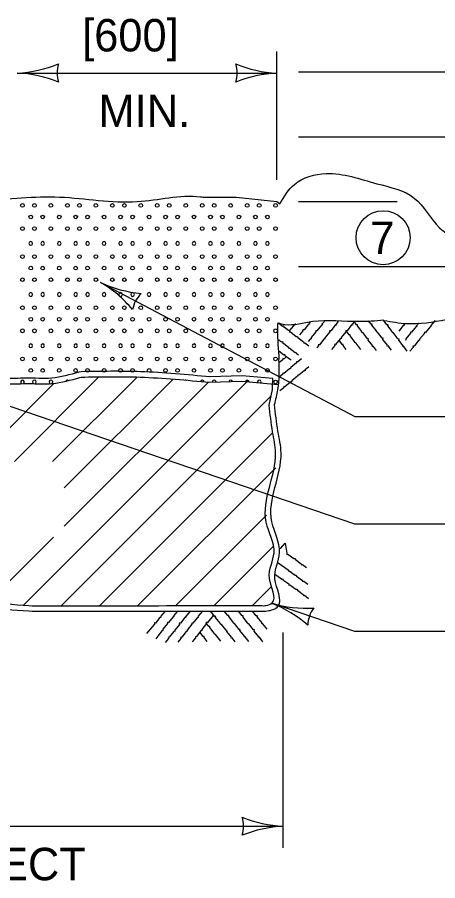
# Model space of a CAD drawing. Extents: x 49991.4 to 50021, y 49987.6 to 50011.4.
# Drawn here: x 50003.835 to 50004.612, y 49988.821 to 49990.418 of the extents above; entities that cross this region are included whole.
import ezdxf

# ---------------------------------------------------------------- set-up
doc = ezdxf.new("R2010")
doc.units = 0
for name, color, linetype in [('Level 1', 7, 'Continuous'), ('Level 2', 7, 'Continuous'), ('Level 3', 7, 'Continuous')]:
    doc.layers.add(name, color=color, linetype=linetype)

msp = doc.modelspace()

# ---------------------------------------------------------------- linework, layer by layer
at = {"layer": 'Level 1'}
for p, q in [((50004.3551, 49990.3172), (50005.5769, 49990.3172)), ((50004.3551, 49990.1972), (50005.5769, 49990.1972)), ((50004.3551, 49990.0772), (50004.5374, 49990.0772)), ((50004.3551, 49989.9572), (50004.5826, 49989.9572)), ((50004.5826, 49989.9572), (50004.6739, 49989.9572)), ((50003.8297, 49989.5967), (50003.9858, 49989.7528)), ((50003.9004, 49989.5967), (50004.0565, 49989.7527)), ((50003.922, 49989.5476), (50004.1231, 49989.7486)), ((50003.953, 49989.7625), (50003.9487, 49989.7618)), ((50003.9509, 49989.752), (50003.953, 49989.7525)), ((50003.759, 49989.5967), (50003.9033, 49989.741)), ((50003.846, 49989.3302), (50004.261, 49989.7452)), ((50003.922, 49989.4769), (50004.1883, 49989.7431)), ((50003.9163, 49989.3297), (50004.3046, 49989.718)), ((50004.3008, 49989.7004), (50004.3071, 49989.7297)), ((50003.987, 49989.3297), (50004.3073, 49989.65)), ((50004.0578, 49989.3298), (50004.3128, 49989.5848)), ((50004.1285, 49989.3298), (50004.296, 49989.4973)), ((50003.7779, 49989.3328), (50003.9018, 49989.4567)), ((50004.1992, 49989.3298), (50004.3083, 49989.4389)), ((50004.27, 49989.3299), (50004.3045, 49989.3644)), ((50004.089, 49989.2957), (50004.0739, 49989.278)), ((50004.0887, 49989.297), (50004.089, 49989.2957))]:
    msp.add_line(p, q, dxfattribs=at)
for points in [[(50004.1787, 49990.0855), (50004.2396, 49990.0851), (50004.315, 49990.0772), (50004.3207, 49990.0731)], [(50004.318, 49989.853), (50004.3256, 49989.8469), (50004.3272, 49989.8477), (50004.3273, 49989.8461), (50004.3381, 49989.838), (50004.3381, 49989.8358), (50004.3401, 49989.8361), (50004.351, 49989.8277), (50004.353, 49989.8277), (50004.3537, 49989.8258), (50004.3645, 49989.8178), (50004.3646, 49989.8158), (50004.3666, 49989.8162), (50004.374, 49989.8104)], [(50004.3487, 49989.8515), (50004.3486, 49989.8514), (50004.3494, 49989.8498), (50004.3478, 49989.8498), (50004.3392, 49989.8394), (50004.3381, 49989.8394)], [(50004.3774, 49989.8554), (50004.3745, 49989.8521), (50004.3753, 49989.8505), (50004.3737, 49989.8505), (50004.3652, 49989.8401), (50004.363, 49989.8401), (50004.3633, 49989.8381), (50004.357, 49989.8305)], [(50004.4029, 49989.8554), (50004.3984, 49989.8502), (50004.3991, 49989.8486), (50004.3975, 49989.8486), (50004.389, 49989.8382), (50004.3868, 49989.8382), (50004.3871, 49989.8362), (50004.3783, 49989.8256), (50004.3782, 49989.8236), (50004.3763, 49989.8229), (50004.3728, 49989.8184)], [(50004.4284, 49989.8551), (50004.424, 49989.85), (50004.4247, 49989.8484), (50004.4231, 49989.8484), (50004.4146, 49989.8379), (50004.4125, 49989.838), (50004.4127, 49989.836), (50004.4039, 49989.8254), (50004.4038, 49989.8234), (50004.402, 49989.8227), (50004.3936, 49989.8123), (50004.3916, 49989.8122), (50004.3919, 49989.8102), (50004.3892, 49989.8069)], [(50004.4583, 49989.8553), (50004.4541, 49989.8504), (50004.4549, 49989.8488), (50004.4533, 49989.8489), (50004.4447, 49989.8384), (50004.4426, 49989.8385), (50004.4428, 49989.8365), (50004.434, 49989.8259), (50004.434, 49989.8239), (50004.4321, 49989.8232), (50004.4237, 49989.8128), (50004.4217, 49989.8127), (50004.422, 49989.8107), (50004.416, 49989.8035)], [(50004.499, 49989.8019), (50004.4937, 49989.8092), (50004.4919, 49989.8088), (50004.4924, 49989.8103), (50004.4841, 49989.821), (50004.4846, 49989.8231), (50004.4826, 49989.8233), (50004.4743, 49989.8343), (50004.4723, 49989.8348), (50004.4721, 49989.8367), (50004.4639, 49989.8473), (50004.4642, 49989.8493), (50004.4622, 49989.8494), (50004.4578, 49989.8552)], [(50004.5268, 49989.8021), (50004.5207, 49989.8104), (50004.5189, 49989.81), (50004.5193, 49989.8116), (50004.5111, 49989.8222), (50004.5116, 49989.8243), (50004.5096, 49989.8246), (50004.5013, 49989.8355), (50004.4993, 49989.836), (50004.4991, 49989.838), (50004.4909, 49989.8485), (50004.4912, 49989.8505), (50004.4892, 49989.8506), (50004.4846, 49989.8567)], [(50004.5561, 49989.8007), (50004.55, 49989.809), (50004.5483, 49989.8086), (50004.5487, 49989.8102), (50004.5404, 49989.8209), (50004.541, 49989.8229), (50004.5389, 49989.8232), (50004.5306, 49989.8341), (50004.5287, 49989.8346), (50004.5285, 49989.8366), (50004.5202, 49989.8471), (50004.5206, 49989.8492), (50004.5185, 49989.8492), (50004.5119, 49989.8581)], [(50004.5519, 49989.8522), (50004.5496, 49989.8495), (50004.5504, 49989.8479), (50004.5488, 49989.8479), (50004.5403, 49989.8374)], [(50004.578, 49989.8529), (50004.5734, 49989.8476), (50004.5742, 49989.8459), (50004.5726, 49989.846), (50004.5641, 49989.8355), (50004.5619, 49989.8356), (50004.5621, 49989.8335), (50004.5533, 49989.823), (50004.5533, 49989.8209), (50004.5528, 49989.8207)], [(50004.6075, 49989.8572), (50004.5991, 49989.8473), (50004.5998, 49989.8457), (50004.5982, 49989.8458), (50004.5897, 49989.8353), (50004.5875, 49989.8353), (50004.5878, 49989.8333), (50004.579, 49989.8227), (50004.5789, 49989.8207), (50004.577, 49989.8201), (50004.5686, 49989.8097), (50004.5666, 49989.8095), (50004.567, 49989.8075), (50004.5609, 49989.8004)], [(50004.4702, 49989.8034), (50004.4608, 49989.8158), (50004.4589, 49989.8163), (50004.4587, 49989.8183), (50004.4504, 49989.8289), (50004.4508, 49989.8309), (50004.4487, 49989.831), (50004.4432, 49989.8384)], [(50004.317, 49989.8228), (50004.3236, 49989.8175), (50004.3252, 49989.8183), (50004.3252, 49989.8167), (50004.336, 49989.8085), (50004.336, 49989.8064), (50004.338, 49989.8067), (50004.3489, 49989.7983), (50004.3509, 49989.7983), (50004.3516, 49989.7964), (50004.3553, 49989.7937)], [(50004.4434, 49989.8035), (50004.4375, 49989.811), (50004.4379, 49989.813), (50004.4358, 49989.8131), (50004.4302, 49989.8207)], [(50004.3181, 49989.8016), (50004.3277, 49989.7938), (50004.3293, 49989.7947), (50004.3293, 49989.7931), (50004.3401, 49989.7849), (50004.3401, 49989.7838)], [(50004.3603, 49989.7862), (50004.3535, 49989.7806), (50004.3514, 49989.781), (50004.3512, 49989.779), (50004.3406, 49989.7703), (50004.3401, 49989.7683), (50004.3382, 49989.7681), (50004.3279, 49989.7594), (50004.3259, 49989.7597), (50004.3259, 49989.7577), (50004.3186, 49989.7518)], [(50004.3325, 49989.79), (50004.3283, 49989.7864), (50004.3263, 49989.7867), (50004.3263, 49989.7846), (50004.3189, 49989.7788)], [(50004.3741, 49989.7714), (50004.3671, 49989.7659), (50004.3676, 49989.7641), (50004.366, 49989.7645), (50004.3556, 49989.7559), (50004.3535, 49989.7563), (50004.3533, 49989.7543), (50004.3427, 49989.7456), (50004.3422, 49989.7436), (50004.3403, 49989.7434), (50004.33, 49989.7347), (50004.328, 49989.735), (50004.328, 49989.7329), (50004.3207, 49989.7271)], [(50004.3075, 49989.7498), (50004.2508, 49989.7548), (50004.1907, 49989.7529)], [(50004.191, 49989.7429), (50004.2505, 49989.7448), (50004.3174, 49989.7388)], [(50004.3192, 49989.4364), (50004.3206, 49989.4353), (50004.3222, 49989.4362), (50004.3302, 49989.4455), (50004.3332, 49989.4267), (50004.3333, 49989.4246), (50004.3353, 49989.4249), (50004.3464, 49989.4168), (50004.3484, 49989.4169), (50004.3492, 49989.415), (50004.3601, 49989.4073), (50004.3603, 49989.4053), (50004.3623, 49989.4058), (50004.3698, 49989.4002)], [(50004.3175, 49989.409), (50004.3356, 49989.396), (50004.3356, 49989.3939), (50004.3377, 49989.3942), (50004.3487, 49989.3861), (50004.3508, 49989.3862), (50004.3515, 49989.3844), (50004.3625, 49989.3766), (50004.3627, 49989.3746), (50004.3647, 49989.3751), (50004.3721, 49989.3695)], [(50004.3125, 49989.3876), (50004.3243, 49989.3785), (50004.3259, 49989.3794), (50004.326, 49989.3778), (50004.3369, 49989.3699), (50004.337, 49989.3678), (50004.339, 49989.3681), (50004.3501, 49989.36), (50004.3521, 49989.3601), (50004.3529, 49989.3582), (50004.3638, 49989.3505), (50004.364, 49989.3485), (50004.3661, 49989.349), (50004.3735, 49989.3433)], [(50004.1082, 49989.3198), (50004.0997, 49989.3097), (50004.1005, 49989.3081), (50004.0989, 49989.3081), (50004.0905, 49989.2975), (50004.0884, 49989.2975)], [(50004.1314, 49989.3198), (50004.1239, 49989.3109), (50004.1247, 49989.3093), (50004.1231, 49989.3093), (50004.1148, 49989.2987), (50004.1126, 49989.2987), (50004.1129, 49989.2967), (50004.1043, 49989.286), (50004.1043, 49989.2839), (50004.1024, 49989.2832), (50004.0912, 49989.2687)], [(50004.1545, 49989.3198), (50004.1458, 49989.3094), (50004.1466, 49989.3078), (50004.145, 49989.3078), (50004.1367, 49989.2972), (50004.1345, 49989.2972), (50004.1348, 49989.2952), (50004.1262, 49989.2845), (50004.1262, 49989.2825), (50004.1243, 49989.2818), (50004.1161, 49989.2712), (50004.1141, 49989.271), (50004.1145, 49989.269), (50004.1086, 49989.2618)], [(50004.1773, 49989.3198), (50004.1688, 49989.3097), (50004.1697, 49989.3081), (50004.1681, 49989.3081), (50004.1597, 49989.2975), (50004.1576, 49989.2975), (50004.1578, 49989.2955), (50004.1492, 49989.2847), (50004.1492, 49989.2827), (50004.1474, 49989.282), (50004.1392, 49989.2714), (50004.1372, 49989.2713), (50004.1375, 49989.2693), (50004.1316, 49989.2621)], [(50004.2378, 49989.2631), (50004.2324, 49989.2702), (50004.2306, 49989.2698), (50004.231, 49989.2714), (50004.2225, 49989.2819), (50004.223, 49989.284), (50004.221, 49989.2842), (50004.2125, 49989.295), (50004.2105, 49989.2954), (50004.2103, 49989.2974), (50004.2018, 49989.3078), (50004.2021, 49989.3098), (50004.2001, 49989.3099), (50004.1925, 49989.3198)], [(50004.2629, 49989.2638), (50004.2566, 49989.272), (50004.2549, 49989.2716), (50004.2552, 49989.2731), (50004.2468, 49989.2836), (50004.2473, 49989.2857), (50004.2452, 49989.2859), (50004.2367, 49989.2967), (50004.2347, 49989.2972), (50004.2345, 49989.2992), (50004.226, 49989.3095), (50004.2263, 49989.3115), (50004.2243, 49989.3116), (50004.2178, 49989.3199)], [(50004.2893, 49989.263), (50004.283, 49989.2712), (50004.2813, 49989.2708), (50004.2816, 49989.2723), (50004.2732, 49989.2828), (50004.2737, 49989.2849), (50004.2716, 49989.2851), (50004.2631, 49989.2959), (50004.2612, 49989.2964), (50004.2609, 49989.2983), (50004.2525, 49989.3087), (50004.2528, 49989.3107), (50004.2507, 49989.3108), (50004.2438, 49989.3199)], [(50004.2972, 49989.286), (50004.2893, 49989.296), (50004.2873, 49989.2965), (50004.2871, 49989.2985), (50004.2786, 49989.3089), (50004.2789, 49989.3109), (50004.2768, 49989.3109), (50004.27, 49989.3199)], [(50004.1978, 49989.3129), (50004.1959, 49989.3108), (50004.1968, 49989.3092), (50004.1951, 49989.3092), (50004.1868, 49989.2986), (50004.1847, 49989.2986), (50004.1849, 49989.2965), (50004.1763, 49989.2858), (50004.1763, 49989.2838), (50004.1745, 49989.2831), (50004.1663, 49989.2725), (50004.1643, 49989.2724), (50004.1646, 49989.2704), (50004.1587, 49989.2631)], [(50004.2111, 49989.2641), (50004.2015, 49989.2763), (50004.1995, 49989.2768), (50004.1993, 49989.2787), (50004.1908, 49989.2891), (50004.1911, 49989.2911), (50004.1891, 49989.2912), (50004.1834, 49989.2985)], [(50004.1863, 49989.2636), (50004.1803, 49989.271), (50004.1806, 49989.273), (50004.1785, 49989.273), (50004.1727, 49989.2806)]]:
    msp.add_lwpolyline(points, dxfattribs=at)
for centre in [(50003.8446, 49990.07), (50003.8668, 49990.07), (50003.8972, 49990.07), (50003.9277, 49990.07), (50003.9499, 49990.07), (50003.9803, 49990.07), (50004.0108, 49990.07), (50004.033, 49990.07), (50004.0634, 49990.07), (50004.0939, 49990.07), (50004.1161, 49990.07), (50004.1465, 49990.07), (50004.177, 49990.07), (50004.1992, 49990.07), (50004.2296, 49990.07), (50004.2601, 49990.07), (50004.2823, 49990.07), (50004.3127, 49990.07), (50003.8599, 49990.0487), (50003.882, 49990.0487), (50003.9125, 49990.0487), (50003.9125, 49990.0487), (50003.943, 49990.0487), (50003.9651, 49990.0487), (50003.9956, 49990.0487), (50003.9956, 49990.0487), (50004.0261, 49990.0487), (50004.0482, 49990.0487), (50004.0787, 49990.0487), (50004.0787, 49990.0487), (50004.1092, 49990.0487), (50004.1313, 49990.0487), (50004.1618, 49990.0487), (50004.1618, 49990.0487), (50004.1923, 49990.0487), (50004.2144, 49990.0487), (50004.2449, 49990.0487), (50004.2449, 49990.0487), (50004.2754, 49990.0487), (50004.2975, 49990.0487), (50003.8446, 49990.0273), (50003.8668, 49990.0273), (50003.8972, 49990.0273), (50003.9277, 49990.0273), (50003.9499, 49990.0273), (50003.9803, 49990.0273), (50004.0108, 49990.0273), (50004.033, 49990.0273), (50004.0634, 49990.0273), (50004.0939, 49990.0273), (50004.1161, 49990.0273), (50004.1465, 49990.0273), (50004.177, 49990.0273), (50004.1992, 49990.0273), (50004.2296, 49990.0273), (50004.2601, 49990.0273), (50004.2823, 49990.0273), (50004.3127, 49990.0273), (50003.8446, 49989.9754), (50003.8668, 49989.9754), (50003.8972, 49989.9754), (50003.9277, 49989.9754), (50003.9499, 49989.9754), (50003.9803, 49989.9754), (50004.0108, 49989.9754), (50004.033, 49989.9754), (50004.0634, 49989.9754), (50004.0939, 49989.9754), (50004.1161, 49989.9754), (50004.1465, 49989.9754), (50004.177, 49989.9754), (50004.1992, 49989.9754), (50004.2296, 49989.9754), (50004.2601, 49989.9754), (50004.2823, 49989.9754), (50004.3127, 49989.9754), (50003.8599, 49989.9541), (50003.882, 49989.9541), (50003.9125, 49989.9541), (50003.9125, 49989.9541), (50003.943, 49989.9541), (50003.9651, 49989.9541), (50003.9956, 49989.9541), (50003.9956, 49989.9541), (50004.0261, 49989.9541), (50004.0482, 49989.9541), (50004.0787, 49989.9541), (50004.0787, 49989.9541), (50004.1092, 49989.9541), (50004.1313, 49989.9541), (50004.1618, 49989.9541), (50004.1618, 49989.9541), (50004.1923, 49989.9541), (50004.2144, 49989.9541), (50004.2449, 49989.9541), (50004.2449, 49989.9541), (50004.2754, 49989.9541), (50004.2975, 49989.9541), (50003.8446, 49989.9327), (50003.8668, 49989.9327), (50003.8972, 49989.9327), (50003.9277, 49989.9327), (50003.9499, 49989.9327), (50003.9803, 49989.9327), (50004.0108, 49989.9327), (50004.033, 49989.9327), (50004.0634, 49989.9327), (50004.0939, 49989.9327), (50004.1161, 49989.9327), (50004.1465, 49989.9327), (50004.177, 49989.9327), (50004.1992, 49989.9327), (50004.2296, 49989.9327), (50004.2601, 49989.9327), (50004.2823, 49989.9327), (50004.3127, 49989.9327), (50003.8446, 49989.8808), (50003.8668, 49989.8808), (50003.8972, 49989.8808), (50003.9277, 49989.8808), (50003.9499, 49989.8808), (50003.9803, 49989.8808), (50004.0108, 49989.8808), (50004.033, 49989.8808), (50004.0634, 49989.8808), (50004.0939, 49989.8808), (50004.1161, 49989.8808), (50004.1465, 49989.8808), (50004.177, 49989.8808), (50004.1992, 49989.8808), (50004.2296, 49989.8808), (50004.2601, 49989.8808), (50004.2823, 49989.8808), (50004.3127, 49989.8808), (50003.8599, 49989.8595), (50003.882, 49989.8595), (50003.9125, 49989.8595), (50003.9125, 49989.8595), (50003.943, 49989.8595), (50003.9651, 49989.8595), (50003.9956, 49989.8595), (50003.9956, 49989.8595), (50004.0261, 49989.8595), (50004.0482, 49989.8595), (50004.0787, 49989.8595), (50004.0787, 49989.8595), (50004.1092, 49989.8595), (50004.1313, 49989.8595), (50004.1618, 49989.8595), (50004.1618, 49989.8595), (50004.1923, 49989.8595), (50004.2144, 49989.8595), (50004.2449, 49989.8595), (50004.2449, 49989.8595), (50004.2754, 49989.8595), (50004.2975, 49989.8595), (50003.8446, 49989.8381), (50003.8668, 49989.8381), (50003.8972, 49989.8381), (50003.9277, 49989.8381), (50003.9499, 49989.8381), (50003.9803, 49989.8381), (50004.0108, 49989.8381), (50004.033, 49989.8381), (50004.0634, 49989.8381), (50004.0939, 49989.8381), (50004.1161, 49989.8381), (50004.1465, 49989.8381), (50004.177, 49989.8381), (50004.1992, 49989.8381), (50004.2296, 49989.8381), (50004.2601, 49989.8381), (50004.2823, 49989.8381), (50004.3127, 49989.8381), (50003.8446, 49989.7862), (50003.8668, 49989.7862), (50003.8972, 49989.7862), (50003.9277, 49989.7862), (50003.9499, 49989.7862), (50003.9803, 49989.7862), (50004.0108, 49989.7862), (50004.033, 49989.7862), (50004.0634, 49989.7862), (50004.0939, 49989.7862), (50004.1161, 49989.7862), (50004.1465, 49989.7862), (50004.177, 49989.7862), (50004.1992, 49989.7862), (50004.2296, 49989.7862), (50004.2601, 49989.7862), (50004.2823, 49989.7862), (50004.3127, 49989.7862), (50003.8599, 49989.7649), (50003.882, 49989.7649), (50003.9125, 49989.7649), (50003.9125, 49989.7649), (50003.943, 49989.7649), (50003.9651, 49989.7649), (50003.9956, 49989.7649), (50003.9956, 49989.7649), (50004.0261, 49989.7649), (50004.0482, 49989.7649), (50004.0787, 49989.7649), (50004.0787, 49989.7649), (50004.1092, 49989.7649), (50004.1313, 49989.7649), (50004.1618, 49989.7649), (50004.1618, 49989.7649), (50004.1923, 49989.7649), (50004.2144, 49989.7649), (50004.2449, 49989.7649), (50004.2449, 49989.7649), (50004.2754, 49989.7649), (50004.2975, 49989.7649), (50004.3127, 49989.7435)]:
    msp.add_circle(centre, 0.00341, dxfattribs=at)
for centre, start, end in [((50003.8599, 49989.9999), 0, 180), ((50003.882, 49989.9999), 0, 180), ((50003.9125, 49989.9999), 0, 180), ((50003.943, 49989.9999), 0, 180), ((50003.9651, 49989.9999), 0, 180), ((50003.9956, 49989.9999), 0, 180), ((50004.0261, 49989.9999), 0, 180), ((50004.0482, 49989.9999), 0, 180), ((50004.0787, 49989.9999), 0, 180), ((50004.1092, 49989.9999), 0, 180), ((50004.1313, 49989.9999), 0, 180), ((50004.1618, 49989.9999), 0, 180), ((50004.1923, 49989.9999), 0, 180), ((50004.2144, 49989.9999), 0, 180), ((50004.2449, 49989.9999), 0, 180), ((50004.2754, 49989.9999), 0, 180), ((50004.2975, 49989.9999), 0, 180), ((50003.8599, 49989.9998), 180, 0), ((50003.882, 49989.9998), 180, 0), ((50003.9125, 49989.9998), 180, 0), ((50003.9125, 49989.9998), 180, 0), ((50003.943, 49989.9998), 180, 0), ((50003.9651, 49989.9998), 180, 0), ((50003.9956, 49989.9998), 180, 0), ((50003.9956, 49989.9998), 180, 0), ((50004.0261, 49989.9998), 180, 0), ((50004.0482, 49989.9998), 180, 0), ((50004.0787, 49989.9998), 180, 0), ((50004.0787, 49989.9998), 180, 0), ((50004.1092, 49989.9998), 180, 0), ((50004.1313, 49989.9998), 180, 0), ((50004.1618, 49989.9998), 180, 0), ((50004.1618, 49989.9998), 180, 0), ((50004.1923, 49989.9998), 180, 0), ((50004.2144, 49989.9998), 180, 0), ((50004.2449, 49989.9998), 180, 0), ((50004.2449, 49989.9998), 180, 0), ((50004.2754, 49989.9998), 180, 0), ((50004.2975, 49989.9998), 180, 0), ((50003.8599, 49989.9053), 0, 180), ((50003.882, 49989.9053), 0, 180), ((50003.9125, 49989.9053), 0, 180), ((50003.943, 49989.9053), 0, 180), ((50003.9651, 49989.9053), 0, 180), ((50003.9956, 49989.9053), 0, 180), ((50004.0261, 49989.9053), 0, 180), ((50004.0482, 49989.9053), 0, 180), ((50004.0787, 49989.9053), 0, 180), ((50004.1092, 49989.9053), 0, 180), ((50004.1313, 49989.9053), 0, 180), ((50004.1618, 49989.9053), 0, 180), ((50004.1923, 49989.9053), 0, 180), ((50004.2144, 49989.9053), 0, 180), ((50004.2449, 49989.9053), 0, 180), ((50004.2754, 49989.9053), 0, 180), ((50004.2975, 49989.9053), 0, 180), ((50003.8599, 49989.9052), 180, 0), ((50003.882, 49989.9052), 180, 0), ((50003.9125, 49989.9052), 180, 0), ((50003.9125, 49989.9052), 180, 0), ((50003.943, 49989.9052), 180, 0), ((50003.9651, 49989.9052), 180, 0), ((50003.9956, 49989.9052), 180, 0), ((50003.9956, 49989.9052), 180, 0), ((50004.0261, 49989.9052), 180, 0), ((50004.0482, 49989.9052), 180, 0), ((50004.0787, 49989.9052), 180, 0), ((50004.0787, 49989.9052), 180, 0), ((50004.1092, 49989.9052), 180, 0), ((50004.1313, 49989.9052), 180, 0), ((50004.1618, 49989.9052), 180, 0), ((50004.1618, 49989.9052), 180, 0), ((50004.1923, 49989.9052), 180, 0), ((50004.2144, 49989.9052), 180, 0), ((50004.2449, 49989.9052), 180, 0), ((50004.2449, 49989.9052), 180, 0), ((50004.2754, 49989.9052), 180, 0), ((50004.2975, 49989.9052), 180, 0), ((50003.8599, 49989.8107), 0, 180), ((50003.882, 49989.8107), 0, 180), ((50003.9125, 49989.8107), 0, 180), ((50003.943, 49989.8107), 0, 180), ((50003.9651, 49989.8107), 0, 180), ((50003.9956, 49989.8107), 0, 180), ((50004.0261, 49989.8107), 0, 180), ((50004.0482, 49989.8107), 0, 180), ((50004.0787, 49989.8107), 0, 180), ((50004.1092, 49989.8107), 0, 180), ((50004.1313, 49989.8107), 0, 180), ((50004.1618, 49989.8107), 0, 180), ((50004.1923, 49989.8107), 0, 180), ((50004.2144, 49989.8107), 0, 180), ((50004.2449, 49989.8107), 0, 180), ((50004.2754, 49989.8107), 0, 180), ((50004.2975, 49989.8107), 0, 180), ((50003.8599, 49989.8106), 180, 0), ((50003.882, 49989.8106), 180, 0), ((50003.9125, 49989.8106), 180, 0), ((50003.9125, 49989.8106), 180, 0), ((50003.943, 49989.8106), 180, 0), ((50003.9651, 49989.8106), 180, 0), ((50003.9956, 49989.8106), 180, 0), ((50003.9956, 49989.8106), 180, 0), ((50004.0261, 49989.8106), 180, 0), ((50004.0482, 49989.8106), 180, 0), ((50004.0787, 49989.8106), 180, 0), ((50004.0787, 49989.8106), 180, 0), ((50004.1092, 49989.8106), 180, 0), ((50004.1313, 49989.8106), 180, 0), ((50004.1618, 49989.8106), 180, 0), ((50004.1618, 49989.8106), 180, 0), ((50004.1923, 49989.8106), 180, 0), ((50004.2144, 49989.8106), 180, 0), ((50004.2449, 49989.8106), 180, 0), ((50004.2449, 49989.8106), 180, 0), ((50004.2754, 49989.8106), 180, 0), ((50004.2975, 49989.8106), 180, 0), ((50003.8446, 49989.7435), 300.098, 239.902), ((50003.8668, 49989.7435), 279.7998, 256.085), ((50003.8972, 49989.7435), 295.6123, 257.0235), ((50003.9277, 49989.7435), 62.7279, 145.6668), ((50004.1465, 49989.7435), 59.2367, 110.8049), ((50004.177, 49989.7435), 3.2422, 167.341), ((50004.1992, 49989.7435), 355.6509, 188.0141), ((50004.2296, 49989.7435), 12.1054, 171.5596), ((50004.2601, 49989.7435), 1.9005, 167.8952), ((50004.2823, 49989.7435), 327.777, 202.0186)]:
    msp.add_arc(centre, 0.00341, start, end, dxfattribs=at)
for points in [[(50004.3207, 49990.0731), (50004.3474, 49990.109), (50004.4062, 49990.129), (50004.4996, 49990.1103), (50004.5691, 49990.0836), (50004.6158, 49990.0289), (50004.6905, 49989.9808), (50004.7493, 49989.9261), (50004.8094, 49989.898), (50004.8574, 49989.8753)], [(50003.7722, 49990.0774), (50003.9134, 49990.0855), (50004.057, 49990.0772), (50004.1739, 49990.0861), (50004.1787, 49990.0855)], [(50004.3165, 49989.853), (50004.33, 49989.85), (50004.3813, 49989.8557), (50004.4668, 49989.8557), (50004.5124, 49989.8582)], [(50004.3165, 49989.853), (50004.3162, 49989.8404), (50004.3189, 49989.7851)], [(50004.5131, 49989.8575), (50004.5552, 49989.8516), (50004.6278, 49989.8588)], [(50004.3107, 49989.7016), (50004.3171, 49989.7296), (50004.3189, 49989.7851)], [(50003.9487, 49989.7618), (50003.8987, 49989.7506), (50003.8504, 49989.7506), (50003.8141, 49989.7506), (50003.7397, 49989.7673), (50003.6623, 49989.7509), (50003.5951, 49989.7509)], [(50004.1918, 49989.7529), (50004.0627, 49989.7625), (50003.953, 49989.7625)], [(50003.5951, 49989.7409), (50003.6633, 49989.7409), (50003.7397, 49989.7571), (50003.813, 49989.7406), (50003.8504, 49989.7406), (50003.8998, 49989.7406), (50003.9509, 49989.752)], [(50003.953, 49989.7525), (50004.0623, 49989.7525), (50004.191, 49989.7429)], [(50004.3071, 49989.7297), (50004.3071, 49989.7309), (50004.3075, 49989.7498)], [(50004.285, 49989.3199), (50004.2972, 49989.3201), (50004.3171, 49989.3286), (50004.3114, 49989.3797), (50004.32, 49989.428), (50004.3057, 49989.4848), (50004.3228, 49989.6126), (50004.3171, 49989.6524), (50004.3107, 49989.7016)], [(50004.285, 49989.3299), (50004.2951, 49989.3301), (50004.3063, 49989.3349), (50004.3013, 49989.38), (50004.3098, 49989.4276), (50004.2955, 49989.4842), (50004.3127, 49989.6126), (50004.3072, 49989.6511), (50004.3008, 49989.7004)], [(50003.2628, 49989.3271), (50003.3427, 49989.33), (50003.443, 49989.33), (50003.5365, 49989.3244), (50003.6136, 49989.3329), (50003.7161, 49989.3244), (50003.7729, 49989.3329), (50003.8563, 49989.33), (50003.9084, 49989.3297)], [(50003.263, 49989.3171), (50003.3429, 49989.32), (50003.4427, 49989.32), (50003.5367, 49989.3143), (50003.6137, 49989.3228), (50003.7164, 49989.3143), (50003.7734, 49989.3228), (50003.8561, 49989.32), (50003.9083, 49989.3197)], [(50003.9083, 49989.3197), (50004.1585, 49989.3198), (50004.285, 49989.3199)], [(50003.9084, 49989.3297), (50004.1585, 49989.3298), (50004.285, 49989.3299)]]:
    msp.add_spline(points, degree=3, dxfattribs=at)
at = {"layer": 'Level 2'}
msp.add_circle((50004.5115, 49990.0103), 0.05, dxfattribs=at)
at = {"layer": 'Level 3'}
for p, q in [((50004.3151, 49990.1172), (50004.3151, 49990.3549)), ((50003.8351, 49990.3149), (50004.3151, 49990.3149)), ((50003.9888, 49989.9277), (50004.4591, 49989.6797)), ((50004.4589, 49989.4807), (50003.5027, 49989.8071)), ((50004.4591, 49989.6797), (50005.491, 49989.6806)), ((50005.611, 49989.4807), (50004.4589, 49989.4807)), ((50004.4589, 49989.2818), (50004.3057, 49989.3341)), ((50004.3268, 49988.8819), (50004.3268, 49989.2804)), ((50005.5796, 49989.2818), (50004.4589, 49989.2818)), ((50002.3811, 49988.9219), (50004.3268, 49988.9219))]:
    msp.add_line(p, q, dxfattribs=at)
for centre, radius, start, end in [((50003.8236, 49990.5476), 0.233, 272.8273, 292.0772), ((50003.9633, 49990.3149), 0.0548, 162.1388, 197.8612), ((50004.3242, 49990.537), 0.2223, 247.456, 267.6395), ((50004.1869, 49990.3149), 0.0548, 342.1388, 17.8612), ((50003.8259, 49990.0927), 0.2223, 67.456, 87.6395), ((50004.3266, 49990.0822), 0.233, 92.8273, 112.0772), ((50003.8771, 49989.7354), 0.2223, 39.6575, 59.841), ((50004.0871, 49990.1389), 0.233, 245.0288, 264.2786), ((50004.1022, 49989.8679), 0.0548, 134.3403, 170.0627), ((50004.2253, 49989.1268), 0.2223, 48.6075, 68.791), ((50004.37, 49989.558), 0.233, 253.9788, 273.2286), ((50004.4271, 49989.2927), 0.0548, 143.2903, 179.0126), ((50004.336, 49989.144), 0.2223, 247.456, 267.6395), ((50004.1986, 49988.9219), 0.0548, 342.1388, 17.8612), ((50004.3383, 49988.6891), 0.233, 92.8273, 112.0772)]:
    msp.add_arc(centre, radius, start, end, dxfattribs=at)

# ---------------------------------------------------------------- texts
at = {"layer": 'Level 2'}
for s, p in [('[600]', (50003.955, 49990.3549)), ('MIN.', (50003.9853, 49990.2149)), ('7', (50004.4877, 49989.9803)), ('OR AS DIRECTED BY THE PROJECT', (50002.5708, 49988.8219))]:
    msp.add_text(s, height=0.06, dxfattribs=at).set_placement(p)

doc.saveas('drawing.dxf')
